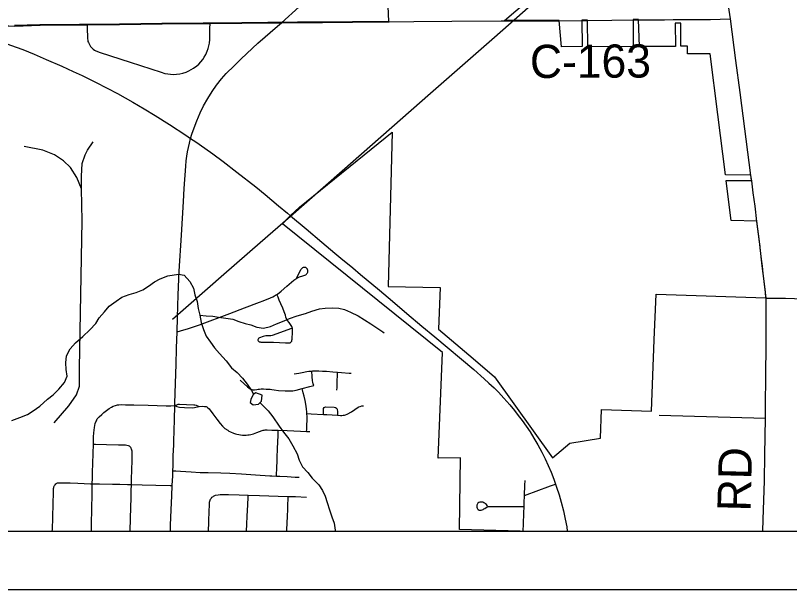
# Model space of a CAD drawing. Extents: x 0 to 34, y 0 to 22.
# Drawn here: x 16.463 to 17.787, y 13.024 to 14.006 of the extents above; entities that cross this region are included whole.
import ezdxf

# ---------------------------------------------------------------- set-up
doc = ezdxf.new("R2010")
doc.units = 0
for name, color, linetype in [('GM_X_City_Street', 7, 'Continuous'), ('GM_X_Corporation', 7, 'Continuous'), ('GM_X_County_Road', 7, 'Continuous'), ('GM_X_County_Road_Text', 7, 'Continuous'), ('GM_X_Minor_Lake', 7, 'Continuous'), ('GM_X_Minor_River', 7, 'Continuous'), ('GM_X_Rail_Line', 7, 'Continuous'), ('GM_X_State_Route', 7, 'Continuous'), ('GM_X_Township_Road', 7, 'Continuous'), ('SH_Data', 7, 'Continuous')]:
    doc.layers.add(name, color=color, linetype=linetype)

msp = doc.modelspace()

# ---------------------------------------------------------------- linework, layer by layer
at = {"layer": 'GM_X_City_Street'}
for points in [[(16.586, 13.9902), (16.5861, 13.9809), (16.5864, 13.9712), (16.5868, 13.9662), (16.5871, 13.9638), (16.5875, 13.9619), (16.5881, 13.96), (16.5893, 13.9576), (16.5906, 13.9552), (16.5918, 13.9534), (16.5931, 13.9518), (16.595, 13.9498), (16.5966, 13.9483), (16.5987, 13.9469), (16.6011, 13.9456), (16.6084, 13.943), (16.6594, 13.9264), (16.7125, 13.9091), (16.719, 13.9072), (16.7239, 13.9063), (16.7287, 13.9057), (16.7342, 13.9055), (16.7391, 13.9057), (16.7446, 13.9065), (16.7499, 13.9077), (16.7552, 13.9094), (16.7597, 13.9113), (16.7641, 13.9135), (16.7682, 13.9161), (16.7737, 13.9201), (16.7769, 13.9229), (16.7806, 13.9269), (16.7837, 13.9308), (16.7864, 13.9348), (16.7891, 13.9397), (16.7916, 13.9453), (16.7932, 13.9499), (16.7943, 13.954), (16.7952, 13.9589), (16.7958, 13.965), (16.796, 13.9691), (16.796, 13.973), (16.796, 13.9842), (16.7962, 13.9926)], [(16.7398, 13.4646), (16.7459, 13.4663), (16.7593, 13.4705), (16.778, 13.477), (16.8301, 13.4964), (16.855, 13.5059), (16.881, 13.5157), (16.8873, 13.5181), (16.8998, 13.5233), (16.9037, 13.525), (16.9064, 13.5264), (16.9084, 13.5274), (16.9104, 13.5287), (16.9115, 13.5295), (16.9179, 13.5344), (16.9278, 13.5429), (16.9396, 13.553), (16.9448, 13.5566), (16.9471, 13.5578), (16.9495, 13.5587), (16.9547, 13.5604), (16.9583, 13.5617), (16.9598, 13.5624), (16.9608, 13.563), (16.9615, 13.5637), (16.962, 13.5644), (16.9626, 13.5652), (16.963, 13.566), (16.9633, 13.5669), (16.9635, 13.5681), (16.9635, 13.5693), (16.9634, 13.5703), (16.9632, 13.5712), (16.9627, 13.5723), (16.962, 13.5733), (16.9612, 13.574), (16.9607, 13.5745), (16.96, 13.5748), (16.9589, 13.575), (16.9577, 13.5752), (16.9563, 13.575), (16.9554, 13.5747), (16.9544, 13.5741), (16.9535, 13.5735), (16.9526, 13.5728), (16.9518, 13.5718), (16.9508, 13.5703), (16.9469, 13.563), (16.9441, 13.5569)], [(16.9357, 13.4708), (16.9025, 13.4585), (16.9001, 13.4579), (16.899, 13.4578), (16.8977, 13.4579), (16.8946, 13.4582), (16.8926, 13.4581), (16.8915, 13.4579), (16.8873, 13.4566), (16.8808, 13.4546), (16.8797, 13.454), (16.8792, 13.4535), (16.8785, 13.4525), (16.8781, 13.4514), (16.8781, 13.4507), (16.8783, 13.4495), (16.8789, 13.4487), (16.8795, 13.4482), (16.8802, 13.4478), (16.881, 13.4476), (16.8818, 13.4475), (16.883, 13.4474), (16.905, 13.4471), (16.9255, 13.4462), (16.9316, 13.446), (16.933, 13.4461), (16.9344, 13.4469), (16.9349, 13.4475), (16.9355, 13.4482), (16.9359, 13.4491), (16.9363, 13.4506), (16.9365, 13.4522), (16.9373, 13.4646), (16.9373, 13.4689), (16.9371, 13.4706), (16.9365, 13.4725), (16.936, 13.4739), (16.9348, 13.4758), (16.9313, 13.4808), (16.9286, 13.4842), (16.9275, 13.4857), (16.9268, 13.4872), (16.926, 13.49), (16.9251, 13.4935), (16.9242, 13.4964), (16.9232, 13.4992), (16.9207, 13.5053), (16.9173, 13.513), (16.9147, 13.5192), (16.9125, 13.524), (16.9104, 13.5287)], [(16.9404, 13.3927), (16.948, 13.3941), (16.9538, 13.3952), (16.9617, 13.3968), (16.965, 13.3973), (16.9683, 13.3977), (16.9703, 13.3978), (16.972, 13.3979), (16.9824, 13.398), (16.9888, 13.3977), (16.9954, 13.3974), (17.0062, 13.3963), (17.0144, 13.3957), (17.0209, 13.3952), (17.0343, 13.3943), (17.0374, 13.3941)], [(16.9735, 13.3732), (16.9727, 13.3761), (16.9721, 13.3785), (16.9717, 13.3808), (16.9714, 13.3827), (16.971, 13.3865), (16.9708, 13.3901), (16.9705, 13.3959), (16.9703, 13.3978)], [(17.0132, 13.365), (17.0134, 13.3696), (17.0135, 13.3748), (17.0137, 13.3815), (17.0141, 13.3895), (17.0143, 13.3932), (17.0144, 13.3957)], [(16.8478, 13.3823), (16.8547, 13.3756), (16.8604, 13.3705), (16.8629, 13.3686), (16.8645, 13.3675), (16.8662, 13.3666), (16.868, 13.366), (16.8693, 13.3657), (16.8707, 13.3657), (16.8721, 13.3658), (16.8761, 13.3663), (16.8783, 13.3666), (16.8808, 13.367), (16.8839, 13.3672), (16.8874, 13.3673), (16.8921, 13.367), (16.8988, 13.3665), (16.9019, 13.3662), (16.906, 13.3657), (16.9134, 13.3643)], [(16.9134, 13.3643), (16.9246, 13.3637), (16.9278, 13.3636), (16.9309, 13.3636), (16.9337, 13.3637), (16.9376, 13.3641), (16.9434, 13.3653), (16.9537, 13.368), (16.9669, 13.3715), (16.9735, 13.3732)], [(16.9615, 13.2945), (16.9616, 13.2979), (16.9618, 13.3049), (16.9621, 13.3136), (16.9621, 13.3195), (16.9619, 13.3249), (16.9618, 13.3281), (16.9613, 13.3325), (16.9607, 13.3374), (16.9589, 13.3473), (16.9571, 13.3546), (16.9555, 13.3607), (16.9537, 13.368)], [(16.6066, 13.3195), (16.6109, 13.3234), (16.6148, 13.3269), (16.6191, 13.3305), (16.6239, 13.3339), (16.6276, 13.3361), (16.6308, 13.3376), (16.6343, 13.3389), (16.6377, 13.3398), (16.6405, 13.3401), (16.6442, 13.3403), (16.6517, 13.3402), (16.6648, 13.3398), (16.666, 13.3398), (16.6905, 13.3391), (16.7214, 13.3384), (16.7293, 13.3383), (16.736, 13.3387)], [(16.736, 13.3387), (16.7394, 13.3402), (16.7416, 13.3408), (16.7439, 13.341), (16.7557, 13.3407), (16.7684, 13.3401), (16.7705, 13.3398), (16.7726, 13.3392), (16.7778, 13.3372)], [(16.736, 13.3387), (16.7394, 13.337), (16.7418, 13.3363), (16.7441, 13.3358), (16.7526, 13.3354), (16.7669, 13.335), (16.7696, 13.3353), (16.7721, 13.3357), (16.7778, 13.3372)], [(16.7778, 13.3372), (16.7834, 13.3374), (16.7869, 13.3373), (16.7886, 13.3371), (16.7897, 13.3368), (16.7909, 13.3364), (16.7927, 13.335), (16.7948, 13.3329), (16.8012, 13.3246), (16.8077, 13.3155), (16.8133, 13.308), (16.8175, 13.3033), (16.8218, 13.2996), (16.8264, 13.2963), (16.8282, 13.2951), (16.8314, 13.2935), (16.8366, 13.2912), (16.8396, 13.2902), (16.8422, 13.2895), (16.8454, 13.2889), (16.8483, 13.2884), (16.8517, 13.2882), (16.8546, 13.2881), (16.8579, 13.2881), (16.8608, 13.2884), (16.8631, 13.2887), (16.866, 13.2892), (16.8683, 13.2898), (16.8708, 13.2905), (16.8761, 13.2924), (16.8852, 13.2959), (16.887, 13.2965), (16.8886, 13.2968), (16.8907, 13.2969), (16.8938, 13.2971), (16.9019, 13.2968), (16.913, 13.2963), (16.928, 13.2958), (16.9511, 13.2948), (16.9615, 13.2945), (16.9671, 13.2943)], [(16.9619, 13.3249), (16.9694, 13.3245), (16.9901, 13.3234), (16.996, 13.3231), (17.0144, 13.3221), (17.0195, 13.3219), (17.0218, 13.3219), (17.0242, 13.3221), (17.026, 13.3224), (17.0277, 13.3229), (17.031, 13.3242), (17.0379, 13.3282), (17.0493, 13.3358), (17.051, 13.3366), (17.053, 13.3373), (17.056, 13.338), (17.0585, 13.3382)], [(16.9901, 13.3234), (16.9901, 13.3289), (16.9901, 13.332), (16.9903, 13.3338), (16.9913, 13.3354), (16.9923, 13.3362), (16.9941, 13.3366), (17.0084, 13.3359), (17.0109, 13.3355), (17.0125, 13.3345), (17.0133, 13.3336), (17.0137, 13.3324), (17.014, 13.3281), (17.0144, 13.3221)], [(16.5933, 13.1239), (16.5935, 13.1365), (16.5943, 13.1612), (16.5945, 13.1877), (16.5949, 13.2049), (16.5952, 13.2145), (16.5955, 13.2249), (16.5959, 13.2397), (16.5963, 13.2565), (16.5968, 13.2726), (16.5968, 13.2749), (16.5972, 13.285), (16.5975, 13.292), (16.5979, 13.2967), (16.5985, 13.3013), (16.5991, 13.3043), (16.5999, 13.3077), (16.6009, 13.3109), (16.6019, 13.3128), (16.6034, 13.3158), (16.6066, 13.3195)], [(16.9098, 13.2181), (16.9101, 13.2248), (16.9102, 13.2267), (16.9111, 13.249), (16.9118, 13.2651), (16.9126, 13.2873), (16.913, 13.2963)], [(16.5968, 13.2726), (16.6002, 13.2725), (16.6192, 13.2719), (16.6398, 13.2715), (16.6487, 13.2713), (16.6518, 13.2712), (16.6541, 13.271), (16.656, 13.2706), (16.6577, 13.2697), (16.6587, 13.269), (16.66, 13.2677), (16.661, 13.2662)], [(16.6597, 13.1239), (16.6604, 13.1458), (16.6608, 13.1639), (16.6613, 13.1814), (16.6615, 13.1927), (16.6619, 13.2037), (16.662, 13.2071), (16.6627, 13.2343), (16.6629, 13.2387), (16.6631, 13.2467), (16.6633, 13.2565), (16.6632, 13.2586), (16.663, 13.2608), (16.6627, 13.2624), (16.6622, 13.2638), (16.661, 13.2662)], [(16.7327, 13.2269), (16.7377, 13.2267), (16.7459, 13.2265), (16.7642, 13.2254), (16.7793, 13.2243), (16.7929, 13.2239), (16.8145, 13.2233), (16.83, 13.2229), (16.85, 13.2218), (16.8738, 13.2202), (16.8984, 13.2186), (16.9019, 13.2184), (16.9098, 13.2181), (16.9155, 13.2178), (16.9284, 13.217), (16.9419, 13.2164), (16.9484, 13.2161)], [(16.5265, 13.1239), (16.5266, 13.1268), (16.5272, 13.1471), (16.5277, 13.171), (16.5283, 13.1891), (16.5287, 13.1967), (16.5289, 13.1982), (16.5292, 13.1997), (16.5296, 13.2007), (16.5302, 13.2018), (16.5312, 13.203), (16.5324, 13.2045)], [(16.5324, 13.2045), (16.5334, 13.2054), (16.5345, 13.2059), (16.5354, 13.2063), (16.5379, 13.2065), (16.5429, 13.2066), (16.5571, 13.2062), (16.5703, 13.2057), (16.5919, 13.205), (16.5949, 13.2049), (16.6072, 13.2046), (16.6295, 13.2043), (16.6419, 13.2041), (16.6548, 13.2038), (16.6619, 13.2037), (16.6803, 13.2032), (16.7036, 13.2024), (16.7278, 13.2018), (16.7317, 13.2016)], [(16.8057, 13.1852), (16.81, 13.1861), (16.8134, 13.1865), (16.8173, 13.1866), (16.8276, 13.1863), (16.8463, 13.186), (16.8615, 13.1856), (16.8811, 13.1848), (16.9127, 13.1839), (16.93, 13.1833), (16.9425, 13.1828), (16.9613, 13.1822)], [(16.8588, 13.1239), (16.8593, 13.1357), (16.8598, 13.1492), (16.8606, 13.1689), (16.8613, 13.1822), (16.8615, 13.1856)], [(16.7938, 13.1239), (16.7943, 13.1393), (16.795, 13.1598), (16.7952, 13.1667), (16.7956, 13.1734), (16.7965, 13.177), (16.7972, 13.1786), (16.7979, 13.1798), (16.7995, 13.1817), (16.8009, 13.1827), (16.802, 13.1835), (16.8057, 13.1852)], [(16.9273, 13.1239), (16.9274, 13.1262), (16.9287, 13.1494), (16.9291, 13.1606), (16.9293, 13.1676), (16.9299, 13.1803), (16.93, 13.1833)]]:
    msp.add_lwpolyline(points, dxfattribs=at)
at = {"layer": 'GM_X_Corporation'}
for points in [[(13.4438, 15.6034), (13.4438, 13.1239), (18.8008, 13.1239)], [(15.1283, 13.1239), (17.3265, 13.1239), (17.223, 13.1263), (17.2247, 13.249), (17.1863, 13.2484), (17.194, 13.4295), (16.92, 13.6494), (16.9337, 13.664), (16.949, 13.6782), (17.1078, 13.8063), (17.1008, 13.5426), (17.19, 13.5406), (17.19, 13.5406), (17.1871, 13.4693), (17.2462, 13.4191), (17.2829, 13.388), (17.3821, 13.2491), (17.4117, 13.2742), (17.464, 13.2829), (17.4659, 13.3321), (17.5511, 13.3291), (17.5561, 13.4513), (17.5593, 13.5295), (17.7469, 13.5233), (17.7461, 13.5326), (17.744, 13.5514), (17.7424, 13.5645), (17.7408, 13.5777), (17.7371, 13.609), (17.7358, 13.6193), (17.7314, 13.6542), (17.6875, 13.6556), (17.6835, 13.6867), (17.6788, 13.724), (17.7224, 13.7236), (17.7211, 13.733), (17.6776, 13.7335), (17.6646, 13.837), (17.6516, 13.9404), (17.6126, 13.9408), (17.6126, 13.9535), (17.6016, 13.9535), (17.6015, 13.9932), (17.592, 13.9932), (17.5921, 13.9534), (17.5306, 13.9531), (17.5293, 13.9993), (17.5199, 13.9992), (17.5199, 13.9532), (17.4424, 13.9524), (17.4419, 13.9984), (17.4322, 13.9983), (17.4328, 13.9529), (17.3976, 13.9528), (17.3932, 13.9979), (17.3264, 13.9977), (17.2996, 13.9977), (17.5514, 14.2129)], [(17.0949, 14.1527), (17.1012, 13.9961), (17.0399, 13.9955), (16.9884, 13.995), (16.9457, 13.9945), (16.918, 13.9943), (16.8951, 13.9941), (16.8504, 13.9937), (16.796, 13.9932), (16.7845, 13.9931), (16.714, 13.9924), (16.6414, 13.9914), (16.5858, 13.9907), (16.5731, 13.9906), (16.5054, 13.99), (16.4616, 13.9888)]]:
    msp.add_lwpolyline(points, dxfattribs=at)
at = {"layer": 'GM_X_County_Road'}
for p, q in [((17.3934, 13.9973), (17.4324, 13.9978)), ((17.4324, 13.9978), (17.4421, 13.9979)), ((17.5881, 13.9993), (17.5981, 13.9992)), ((17.7226, 13.723), (17.7213, 13.7325))]:
    msp.add_line(p, q, dxfattribs=at)
for points in [[(17.6861, 14.0007), (17.6815, 14.0347), (17.6727, 14.0966), (17.6701, 14.1176), (17.6673, 14.1398), (17.664, 14.1644), (17.6626, 14.1765), (17.6621, 14.1836), (17.662, 14.1871), (17.6619, 14.1924), (17.6622, 14.2083), (17.663, 14.2342), (17.6635, 14.2478), (17.6639, 14.2594), (17.664, 14.2658), (17.6642, 14.2831), (17.6642, 14.2923), (17.6639, 14.3007), (17.6636, 14.3122)], [(16.7962, 13.9926), (16.8506, 13.9931), (16.8953, 13.9935), (16.9182, 13.9937)], [(16.9182, 13.9937), (16.9459, 13.994), (16.9886, 13.9944), (17.0401, 13.9949), (17.0753, 13.9953)], [(17.0753, 13.9953), (17.1014, 13.9956), (17.1024, 13.9956)], [(17.1024, 13.9956), (17.1449, 13.9961), (17.2095, 13.9964), (17.2942, 13.9972), (17.2998, 13.9972)], [(17.2998, 13.9972), (17.3266, 13.9972), (17.3419, 13.9971), (17.3934, 13.9973)], [(17.4421, 13.9979), (17.4834, 13.9984), (17.5201, 13.9987)], [(17.5201, 13.9987), (17.5295, 13.9987), (17.5305, 13.9987)], [(17.5305, 13.9987), (17.5734, 13.999), (17.5881, 13.9993)], [(17.5981, 13.9992), (17.6321, 13.9992), (17.6519, 13.9996), (17.6686, 14), (17.6861, 14.0007)], [(17.7213, 13.7325), (17.7028, 13.8746), (17.6956, 13.9291), (17.6861, 14.0007)], [(16.4424, 13.9887), (16.4433, 13.9886), (16.4524, 13.9884), (16.4619, 13.9882), (16.5056, 13.9895), (16.5733, 13.9901), (16.586, 13.9902)], [(16.586, 13.9902), (16.6416, 13.9908), (16.7142, 13.9918), (16.7847, 13.9925), (16.7962, 13.9926)], [(17.7316, 13.6537), (17.7283, 13.6797), (17.7252, 13.703), (17.7226, 13.723)], [(17.7471, 13.5227), (17.7463, 13.5321), (17.7442, 13.5508), (17.7424, 13.5649), (17.741, 13.5771), (17.7396, 13.5894), (17.7373, 13.6085), (17.737, 13.6108), (17.736, 13.6188), (17.7316, 13.6537)], [(17.7463, 13.3173), (17.7465, 13.3475), (17.7468, 13.3807), (17.7476, 13.4518), (17.7476, 13.5127), (17.7476, 13.5158), (17.7474, 13.5192), (17.7471, 13.5227)], [(17.7471, 13.5227), (17.752, 13.5227), (17.76, 13.5227), (17.7805, 13.5222), (17.811, 13.5211)], [(17.7415, 13.1239), (17.7422, 13.1438), (17.7443, 13.2099), (17.7452, 13.2545), (17.7463, 13.3173)]]:
    msp.add_lwpolyline(points, dxfattribs=at)
at = {"layer": 'GM_X_Minor_Lake'}
msp.add_line((16.8698, 13.3576), (16.8661, 13.3492), dxfattribs=at)
msp.add_lwpolyline([(16.8661, 13.3492), (16.8646, 13.3439), (16.87, 13.3398), (16.8794, 13.341), (16.8843, 13.346), (16.8853, 13.3563), (16.8743, 13.3603), (16.8698, 13.3576)], dxfattribs=at)
at = {"layer": 'GM_X_Minor_River'}
for points in [[(16.4571, 13.3133), (16.471, 13.3184), (16.4842, 13.3235), (16.494, 13.3297), (16.5049, 13.3378), (16.518, 13.3497), (16.5282, 13.357), (16.5375, 13.3666), (16.5476, 13.3781), (16.5521, 13.3888), (16.5504, 13.4002), (16.5495, 13.412), (16.5505, 13.4237), (16.5568, 13.4356), (16.5662, 13.4463), (16.5789, 13.4571), (16.5906, 13.4683), (16.6007, 13.479), (16.6066, 13.4889), (16.616, 13.4989), (16.6238, 13.5089), (16.6358, 13.5174), (16.6456, 13.5243), (16.6581, 13.5287), (16.6698, 13.5322), (16.6814, 13.5365), (16.6912, 13.5431), (16.701, 13.5504), (16.7111, 13.5555), (16.724, 13.5606), (16.7425, 13.5634), (16.752, 13.5616), (16.7616, 13.5507), (16.7678, 13.5398), (16.7705, 13.5284), (16.7741, 13.5167), (16.7761, 13.505), (16.7789, 13.4936), (16.7813, 13.4807), (16.7852, 13.469), (16.7899, 13.4573), (16.7968, 13.4471), (16.8041, 13.4373), (16.8122, 13.4275), (16.8237, 13.4155), (16.8329, 13.4035), (16.8425, 13.3952), (16.852, 13.3855), (16.8597, 13.3753), (16.8671, 13.3644), (16.8706, 13.3581)], [(16.7789, 13.4936), (16.7895, 13.4922), (16.8012, 13.4916), (16.8107, 13.4902), (16.8232, 13.4884), (16.835, 13.4863), (16.8453, 13.4826), (16.8563, 13.4789), (16.8658, 13.4768), (16.8764, 13.4731), (16.8878, 13.4713), (16.8995, 13.4737), (16.9097, 13.4788), (16.9199, 13.4827), (16.9323, 13.4874), (16.9452, 13.4925), (16.9595, 13.4965), (16.9701, 13.5004), (16.9833, 13.504), (16.9931, 13.5056), (17.0052, 13.5057), (17.0166, 13.5051), (17.0261, 13.5029), (17.0364, 13.4985), (17.0497, 13.4922), (17.0604, 13.4851), (17.071, 13.4788), (17.0813, 13.4717), (17.092, 13.465), (17.0939, 13.4631)], [(16.8817, 13.3433), (16.8958, 13.3294), (16.9035, 13.3193), (16.9147, 13.3034), (16.9216, 13.2929), (16.9308, 13.2816), (16.9378, 13.2695), (16.9455, 13.256), (16.9487, 13.2454), (16.9545, 13.234), (16.9633, 13.2243), (16.971, 13.2145), (16.9821, 13.2032), (16.9886, 13.1934), (16.9933, 13.1836), (16.9964, 13.1726), (17.0008, 13.1601), (17.0047, 13.1484), (17.0086, 13.1375), (17.0102, 13.1257), (17.0106, 13.1239)]]:
    msp.add_lwpolyline(points, dxfattribs=at)
at = {"layer": 'GM_X_Rail_Line'}
for points in [[(16.7318, 13.4863), (16.7594, 13.5105), (16.8199, 13.5635), (16.882, 13.6179), (16.9336, 13.6628), (17.0221, 13.7405), (17.1733, 13.8731), (17.2828, 13.9691), (17.3546, 14.0322), (17.3968, 14.0688), (17.5123, 14.1701), (17.5627, 14.2142), (17.6276, 14.2712), (17.6931, 14.3286), (17.7282, 14.3592), (17.7547, 14.3825), (17.8212, 14.4406)], [(16.5766, 13.7093), (16.5685, 13.7292), (16.5575, 13.7461), (16.5454, 13.7574), (16.5304, 13.7679), (16.5102, 13.7758), (16.4781, 13.782)], [(16.5766, 13.7093), (16.5763, 13.7312), (16.5775, 13.753), (16.5825, 13.7676), (16.5868, 13.7758), (16.5963, 13.79)], [(16.5295, 13.3092), (16.555, 13.3384), (16.5681, 13.3568), (16.5728, 13.3716), (16.5731, 13.4024), (16.5773, 13.6548), (16.5766, 13.7093)]]:
    msp.add_lwpolyline(points, dxfattribs=at)
at = {"layer": 'GM_X_State_Route'}
msp.add_line((16.9286, 13.6679), (16.9339, 13.6634), dxfattribs=at)
for points in [[(16.9182, 13.9937), (16.9486, 14.021), (16.9924, 14.0604), (17.01, 14.0762), (17.016, 14.0816), (17.0216, 14.0865), (17.0243, 14.089), (17.0378, 14.101), (17.0951, 14.1522), (17.0958, 14.1528)], [(16.8376, 13.9203), (16.8497, 13.9322), (16.8782, 13.9587), (16.9116, 13.988), (16.9182, 13.9937)], [(16.3619, 13.9868), (16.3823, 13.9806), (16.395, 13.9765), (16.4098, 13.9715), (16.424, 13.9668), (16.439, 13.9615), (16.455, 13.9557), (16.4758, 13.9478), (16.4953, 13.94), (16.5162, 13.9309), (16.543, 13.9192), (16.5622, 13.9105), (16.5774, 13.9034), (16.6003, 13.8922), (16.6203, 13.8821), (16.6378, 13.8726), (16.6644, 13.8577), (16.6836, 13.8465), (16.7023, 13.835), (16.727, 13.8194), (16.7546, 13.8015), (16.7631, 13.7959)], [(16.7631, 13.7959), (16.7651, 13.8029), (16.7672, 13.8092), (16.7735, 13.8259), (16.7794, 13.8395), (16.7853, 13.8517), (16.7923, 13.864), (16.7997, 13.8761), (16.8071, 13.8867), (16.8159, 13.8978), (16.824, 13.907), (16.8376, 13.9203)], [(16.7508, 13.688), (16.7521, 13.71), (16.7547, 13.7484), (16.7556, 13.7576), (16.7566, 13.7654), (16.7578, 13.7728), (16.7592, 13.7803), (16.761, 13.7879), (16.7631, 13.7959)], [(16.7631, 13.7959), (16.7719, 13.7901), (16.797, 13.7723), (16.801, 13.7694)], [(16.801, 13.7694), (16.8186, 13.7564), (16.8423, 13.7382), (16.8745, 13.7128), (16.8905, 13.7), (16.9136, 13.6806), (16.9286, 13.6679)], [(16.7327, 13.2269), (16.7331, 13.2354), (16.7332, 13.2404), (16.7331, 13.2428), (16.7331, 13.2453), (16.7334, 13.2508), (16.7333, 13.2527), (16.7334, 13.2533), (16.7343, 13.2707), (16.7343, 13.2775), (16.7352, 13.3141), (16.736, 13.3387), (16.7362, 13.3427), (16.7372, 13.3762), (16.7381, 13.4098), (16.7382, 13.4141), (16.7387, 13.4314), (16.7389, 13.4376), (16.7394, 13.4506), (16.7398, 13.4646), (16.7405, 13.4891), (16.7417, 13.5282), (16.7437, 13.5685), (16.7474, 13.63), (16.7508, 13.688)], [(16.9339, 13.6634), (16.9605, 13.6412), (16.9875, 13.6185), (17.0097, 13.5995), (17.0201, 13.5908), (17.0404, 13.5743), (17.0538, 13.5631), (17.086, 13.536), (17.1084, 13.5172), (17.1331, 13.4963), (17.1587, 13.4745), (17.1807, 13.4564), (17.202, 13.4385), (17.2265, 13.4181), (17.2475, 13.4003), (17.2652, 13.3846), (17.2732, 13.3772), (17.282, 13.3689), (17.2895, 13.3615), (17.2989, 13.3514), (17.3091, 13.3397), (17.317, 13.3301), (17.3235, 13.3217), (17.3301, 13.3132), (17.3371, 13.3033), (17.3436, 13.2935), (17.3502, 13.2827), (17.3568, 13.2714), (17.3635, 13.259), (17.3696, 13.2473), (17.3746, 13.2363), (17.3796, 13.2245), (17.3842, 13.2126), (17.3871, 13.2044)], [(16.7284, 13.1239), (16.7288, 13.134), (16.73, 13.16), (16.7311, 13.184), (16.7317, 13.2016), (16.7324, 13.2186), (16.7327, 13.2269)], [(17.3871, 13.2044), (17.389, 13.1991), (17.3932, 13.1861), (17.3968, 13.1735), (17.4006, 13.1584), (17.4037, 13.1444), (17.4062, 13.1309), (17.4072, 13.1239)]]:
    msp.add_lwpolyline(points, dxfattribs=at)
at = {"layer": 'GM_X_Township_Road'}
msp.add_line((17.5642, 13.3224), (17.7463, 13.3173), dxfattribs=at)
for points in [[(17.3341, 13.1845), (17.3348, 13.2023), (17.335, 13.2102)], [(17.3341, 13.1845), (17.3389, 13.1863), (17.3539, 13.1919), (17.3788, 13.2012), (17.3871, 13.2044)], [(17.271, 13.1667), (17.2701, 13.1679), (17.2688, 13.1695), (17.2675, 13.1707), (17.2662, 13.1715), (17.2644, 13.1725), (17.2626, 13.1732), (17.2608, 13.1735), (17.2591, 13.1736), (17.2574, 13.1734), (17.2559, 13.1728), (17.2545, 13.1717), (17.2535, 13.1705), (17.2529, 13.1695), (17.2525, 13.1684), (17.2524, 13.1674), (17.2523, 13.1663), (17.2526, 13.1646), (17.2531, 13.1633), (17.2538, 13.162), (17.2551, 13.1608), (17.2567, 13.1599), (17.2583, 13.1596), (17.2599, 13.1598), (17.2617, 13.1602), (17.2633, 13.1609), (17.2647, 13.1617), (17.2665, 13.1628), (17.2704, 13.1653), (17.2716, 13.1658), (17.2732, 13.1661), (17.2745, 13.1662), (17.2761, 13.1662), (17.2873, 13.166), (17.2991, 13.1661), (17.3193, 13.166), (17.3333, 13.1658)], [(17.3333, 13.1658), (17.3336, 13.1725), (17.3341, 13.1845)], [(17.3319, 13.1239), (17.3323, 13.1361), (17.3329, 13.1546), (17.3333, 13.1658)]]:
    msp.add_lwpolyline(points, dxfattribs=at)
at = {"layer": 'SH_Data'}
for p, q in [((13.4438, 13.1239), (20.2438, 13.1239)), ((13.3438, 13.0239), (20.3438, 13.0239))]:
    msp.add_line(p, q, dxfattribs=at)

# ---------------------------------------------------------------- texts
at = {"layer": 'GM_X_County_Road_Text'}
for s, rotation, p in [('C-163', 0.2737, (17.3435, 13.8991)), ('RD', 88.541, (17.7206, 13.157))]:
    msp.add_text(s, height=0.05682, rotation=rotation, dxfattribs=at).set_placement(p)

doc.saveas('drawing.dxf')
